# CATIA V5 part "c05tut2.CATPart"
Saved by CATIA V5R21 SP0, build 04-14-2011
Part number: Part1
Bounding box of the stored display mesh (mm): x -5 to 20, y -42.072 to 42.072, z -42 to 60
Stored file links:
  D:\CATIA V5R21 E-RESOURCES\CATIA-V5R21\catia-v5r21-prt\c05-catia-v5r20-prt\catia-v5r21-tut-02.CATPart
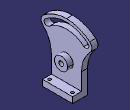
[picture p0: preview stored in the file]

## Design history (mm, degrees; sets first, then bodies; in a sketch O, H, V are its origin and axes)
Body1 (main body)
  Sketch1 on yz-plane, origin (0, 0, 0), H (0, 1, 0), V (0, 0, 1)
    construction line L1 through (0, 25.9857) direction (0, 1)
    arc A1 centre (0, 0) radius 60 from (0, 60) to (-38.5673, 45.9627) ccw
    point P3 (0, 60)
    point P4 (-38.5673, 45.9627)
    point P5 (-25, -42)
    line L2 (-25, -42) -> (-25, -3.6855)
    point P6 (-25, -3.6855)
    arc A2 centre (-32.1394, 38.3022) radius 10 from (-38.5673, 45.9627) to (-39.2828, 31.3043) ccw
    arc A3 centre (-75, -3.6855) radius 50 from (-39.2828, 31.3043) to (-25, -3.6855) cw
    point P9 (-39.2828, 31.3043)
    point P10 (-38.5673, 45.9627)
    point P11 (39.2828, 31.3043)
    point P12 (38.5673, 45.9627)
    arc A4 centre (32.1394, 38.3022) radius 10 from (38.5673, 45.9627) to (39.2828, 31.3043) cw
    point P14 (38.5673, 45.9627)
    point P15 (0, 60)
    arc A5 centre (0, 0) radius 60 from (0, 60) to (38.5673, 45.9627) cw
    point P17 (25, -3.6855)
    arc A6 centre (75, -3.6855) radius 50 from (39.2828, 31.3043) to (25, -3.6855) ccw
    point P19 (25, -42)
    line L3 (25, -42) -> (25, -3.6855)
    line L4 (-25, -42) -> (25, -42)
    construction line L5 (0, 0) -> (32.1394, 38.3022)
    construction line L6 (0, 0) -> (-32.1394, 38.3022)
    radius A5 = 60
    distance H L4 = 42
    radius A3 = 50
    radius A2 = 10
    length L4 = 50
    angle L6 L5 = 80
    vertical: L1 V, L2 V, L3 V
    coincidence: L1 O, P3 L1, A2 P4, A1 P10, P3 P15, P4 P10, P12 P14
    tangency: A3 L2, A2 A3, A2 A1
    symmetry: P9 P11 L1, P10 P12 L1, A2 A4 L1, P4 P14 L1, P3 P15 L1, A1 A5 L1, P6 P17 L1, A3 A6 L1, P5 P19 L1, L2 L3 L1
    horizontal: L4 H
  Pad1: profile Sketch1, direction (1, 0, 0), length 5, mirrored extent
  Sketch2 on end face of Pad1, origin (5, 0, 0), H (0, 1, 0), V (0, 0, 1)
    construction arc A1 centre (0, 0) radius 50 from (32.1394, 38.3022) to (-32.1394, 38.3022) ccw
    point P1 (32.1394, 38.3022)
    point P2 (-32.1394, 38.3022)
    arc A2 centre (32.1394, 38.3022) radius 5 from (35.3533, 42.1324) to (28.9254, 34.472) cw
    arc A3 centre (-32.1394, 38.3022) radius 5 from (-28.9254, 34.472) to (-35.3533, 42.1324) cw
    arc A4 centre (0, 0) radius 45 from (28.9254, 34.472) to (-28.9254, 34.472) ccw
    arc A5 centre (0, 0) radius 55 from (-35.3533, 42.1324) to (35.3533, 42.1324) cw
    reference projected arc E1 centre (-32.1394, 38.3022) radius 10 from (-38.5394, 45.986) to (-39.306, 31.3281) ccw from edge [face of Pad1 from Sketch1.A2 | end face of Pad1]
    reference projected arc E2 centre (32.1394, 38.3022) radius 10 from (39.306, 31.3281) to (38.5394, 45.986) ccw from edge [face of Pad1 from Sketch1.A4 | end face of Pad1]
    construction line L1 (0, 0) -> (32.1394, 38.3022)
    construction line L2 (0, 0) -> (-32.1394, 38.3022)
    radius A3 = 5
    tangency: A4 A3, A3 A5, A5 A2, A2 A4
    concentricity: A4 O, A5 O, P2 E1, P1 E2
  Pocket1: profile Sketch2, direction (-1, 0, 0), through (limit type 3)
  Sketch3 on end face of Pad1, origin (5, 0, 0), H (0, 1, 0), V (0, 0, 1)
    projected line E1 (-25, -42) -> (25, -42) from edge [face of Pad1 from Sketch1.L4 | end face of Pad1]
    line L1 (-25, -42) -> (-25, -32)
    line L2 (25, -42) -> (25, -32)
    line L3 (-25, -32) -> (25, -32)
    length L2 = 10
    vertical: L1 V, L2 V
    horizontal: L3 H
  Pad2: profile Sketch3, direction (1, 0, 0), length 15
  Sketch4 on end face of Pad1, origin (5, 0, 0), H (0, 1, 0), V (0, 0, 1)
    circle A1 centre (0, 0) radius 11
    circle A2 centre (0, 0) radius 4
    radius A2 = 4
    radius A1 = 11
  Pad3: profile Sketch4, direction (1, 0, 0), length 9
  Sketch5 on face of Pad2 from Sketch3.L3, origin (0, 0, -32), H (1, 0, 0), V (0, 1, 0)
    circle A1 centre (14, 19) radius 2.5
    point P1 (14, 19)
    circle A2 centre (14, -19) radius 2.5
    point P2 (14, -19)
    reference projected line E1 (20, 25) -> (20, -25) from edge [face of Pad2 from Sketch3.L3 | end face of Pad2]
    reference projected line E2 (5, -25) -> (20, -25) from edge [face of Pad2 | face of Pad2 from Sketch3.L3]
    reference projected line E3 (5, 38.4) -> (5, 0) from edge [face of Pad1 from Sketch1.A5 | end face of Pad1]
    radius A2 = 2.5
    radius A1 = 2.5
    distance E1 P2 = 6
    distance E2 P2 = 6
    distance P2 P1 = 38
    distance P1 E3 = 9
  Pocket2: profile Sketch5, direction (0, 0, -1), through (limit type 3)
